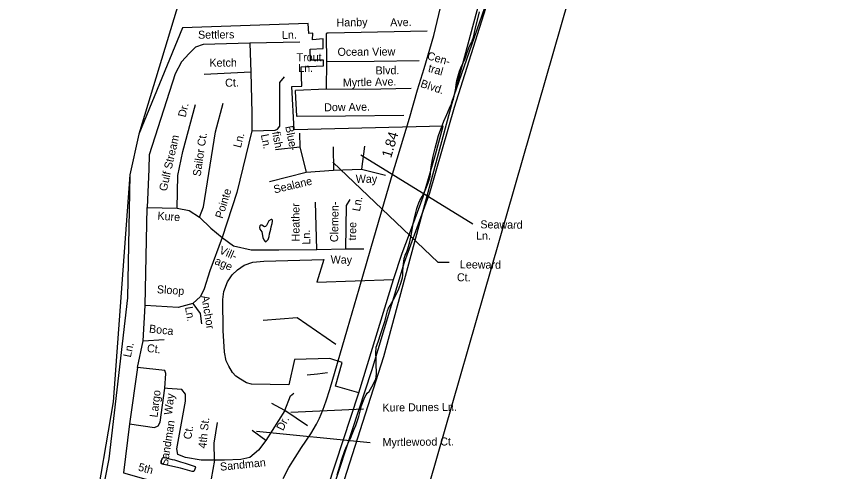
# Model space of a CAD drawing. Extents: x 1945482 to 2853149, y 66427 to 1015778.
# Drawn here: x 2329763 to 2336452, y 93966 to 97692 of the extents above; entities that cross this region are included whole.
import ezdxf

# ---------------------------------------------------------------- set-up
doc = ezdxf.new("R2010")
doc.units = 0
for name, color, linetype in [('Old_Level_10', 7, 'Continuous'), ('Old_Level_17', 7, 'Continuous'), ('Old_Level_28', 7, 'Continuous'), ('Old_Level_35', 7, 'Continuous'), ('Old_Level_48', 7, 'Continuous'), ('Old_Level_49', 7, 'Continuous'), ('Old_Level_52', 7, 'Continuous'), ('Old_Level_60', 7, 'Continuous'), ('Old_Level_61', 7, 'Continuous'), ('Old_Level_63', 7, 'Continuous')]:
    doc.layers.add(name, color=color, linetype=linetype)

msp = doc.modelspace()

# ---------------------------------------------------------------- linework, layer by layer
at = {"layer": 'Old_Level_10'}
for points in [[(2333502.8, 95992.6), (2332586.5, 96555.7)], [(2333310.2, 95677.3), (2333220.6, 95677.3), (2332356, 96500.1)], [(2332609.1, 94478.5), (2332011.8, 94449.5)], [(2332662.2, 94201.1), (2331731.4, 94294.3)]]:
    msp.add_lwpolyline(points, dxfattribs=at)
at = {"layer": 'Old_Level_28'}
msp.add_lwpolyline([(2331948.9, 93909.6), (2331995.8, 93998.4), (2332100.3, 94162.9), (2332175.5, 94275.1), (2332223.2, 94353.5), (2332247.8, 94402.6), (2332275.4, 94468.7), (2332303.1, 94545.6), (2332330.7, 94637.8), (2332395.5, 94853.6), (2332477, 95133.4), (2332572.2, 95460.7), (2332669, 95791.2), (2332838, 96372.2), (2332984, 96859.4), (2333050, 97090), (2333105.3, 97266.8), (2333183.7, 97535.7), (2333295.8, 98007.8)], dxfattribs=at)
at = {"layer": 'Old_Level_35'}
msp.add_line((2332304.7, 97319.1), (2332303, 97095.2), dxfattribs=at)
for points in [[(2333130.1, 97569.9), (2332722.5, 97561.7), (2332318.3, 97555.6), (2332306.3, 97553.5), (2332302.2, 97549.4)], [(2332302.2, 97549.4), (2332302.5, 97541.6), (2332304.7, 97319.1)], [(2332086.6, 97482.2), (2331675.2, 97473.8), (2331293.5, 97461), (2331229.9, 97439.8), (2331179, 97388.9), (2331115.4, 97321), (2331064.5, 97221.7), (2330852.5, 96559.6), (2330848.2, 96440.8), (2330835.5, 96126.7), (2331081.5, 96122.5), (2331085.7, 96389.8), (2331128.1, 96585.1), (2331229.9, 96971.3)], [(2331675.2, 97473.8), (2331683.7, 97234.4), (2331302, 97217.4)], [(2333062.6, 97327), (2332694.8, 97321.4), (2332304.7, 97319.1)], [(2331683.7, 97234.4), (2331692.2, 96899.1), (2331692.2, 96754.8), (2331569.2, 96249.8), (2331450.4, 95882.2), (2331348.7, 95610.6), (2331302, 95462.1), (2331272.3, 95398.4), (2331208.7, 95343.3), (2331089.9, 95309.3), (2330818.5, 95326.3), (2330835.5, 96126.7)], [(2331692.2, 96754.8), (2331883, 96760.8), (2331904.2, 96769.2), (2331921.2, 96794.7), (2331921.2, 97151.2), (2331959.4, 97197.9)], [(2332063.3, 96872.7), (2332061.2, 96876.6), (2332050.9, 97078.7), (2332051, 97084.6)], [(2332303, 97095.2), (2332053.2, 97086.7), (2332051, 97084.6)], [(2332999.2, 97102.3), (2332625, 97094.5), (2332303, 97095.2)], [(2331263.8, 96047.8), (2331297.8, 96132.6), (2331395.3, 96748), (2331458.9, 96981.4)], [(2332939.3, 96881.7), (2332459.4, 96874.9), (2332063.3, 96872.7)], [(2332082.3, 96735.3), (2332086.6, 96620.7), (2331887.3, 96599.5)], [(2332086.6, 96620.7), (2332137.5, 96417)], [(2332358, 96624.9), (2332362.3, 96434)], [(2332616.7, 96629.2), (2332591.3, 96442.5)], [(2331836.4, 96340.6), (2332137.5, 96417), (2332362.3, 96434), (2332591.3, 96442.5), (2332787.7, 96393.3)], [(2332226.5, 95784.6), (2332213.8, 96170.8)], [(2332464, 95788.9), (2332468.3, 96145.4), (2332498, 96192.1)], [(2331081.5, 96122.5), (2331179, 96102.9), (2331263.8, 96047.8), (2331357.1, 95958.6), (2331450.4, 95882.2), (2331543.7, 95814.3), (2331687.9, 95780.4), (2331912.7, 95780.4), (2332226.5, 95784.6), (2332464, 95788.9)], [(2332464, 95788.9), (2332609.9, 95788.9)], [(2331208.7, 95343.3), (2331268.1, 95260.9), (2331280.8, 95176)], [(2330801.6, 95036), (2330818.5, 95326.3)], [(2331785.5, 95205.7), (2332065.4, 95227)], [(2332065.4, 95227), (2332380.5, 95008)], [(2331806.7, 94221.1), (2331747.3, 94140.5), (2331675.2, 94081.1), (2331603.1, 94064.1), (2331467.4, 94059.9), (2331386.8, 94059.9), (2331276.6, 94059.9), (2331149.3, 94081.1), (2331085.7, 94106.5), (2331077.2, 94153.2), (2331149.3, 94543.7), (2331149.3, 94598.9), (2331119.6, 94637), (2331000.9, 94645.5), (2330979.7, 94649.8), (2330988.2, 94768.6), (2330979.7, 94794.1), (2330754.9, 94819.5), (2330801.6, 95036), (2330975.4, 95048.7)], [(2330754.9, 94819.5), (2330691.3, 94356.9), (2330894.9, 94327.2), (2330924.5, 94340), (2330941.5, 94369.7), (2330979.7, 94649.8)], [(2332313.1, 94774.8), (2332230.8, 94764.4), (2332146, 94755.9)], [(2331963.6, 94467.3), (2332010.3, 94586.1), (2332035.7, 94607.3)], [(2331963.6, 94467.3), (2331806.7, 94221.1), (2331696.4, 94301.8)], [(2332149.7, 94341), (2331963.6, 94467.3), (2331857.6, 94522.5)], [(2330691.3, 94356.9), (2330639.8, 93956.6), (2330805, 93910.6), (2330942.7, 93873.9), (2331016.1, 93800.4), (2331057.4, 93658.1), (2331042.2, 93559.4)], [(2331386.8, 94059.9), (2331383.2, 94198.1), (2331410.8, 94368)], [(2331386.8, 94059.9), (2331360.1, 93906.5)]]:
    msp.add_lwpolyline(points, dxfattribs=at)
at = {"layer": 'Old_Level_48'}
for points in [[(2333261.7, 96792.4), (2332039.5, 96763.6), (2332021.5, 97117), (2332101.4, 97120.1), (2332097.1, 97280), (2332280.9, 97287.3), (2332279.1, 97333.2), (2332173, 97335), (2332171.5, 97423), (2332277.3, 97429.2), (2332276.1, 97509.2), (2332190.5, 97499.8), (2332192.3, 97553.9), (2332160.5, 97550.6), (2332155.1, 97634.4), (2331125.7, 97599.6)], [(2331125.7, 97599.6), (2330766.3, 96729.3), (2330693.4, 96396.3), (2330556.8, 94536.2), (2330233, 92650)], [(2332570.7, 94609.9), (2332378.3, 94666.1), (2332432.8, 94858.4), (2332331.4, 94892.4), (2332043.6, 94883), (2331995.8, 94677), (2331689.4, 94683), (2331649, 94693.4), (2331599.9, 94721.4), (2331560.8, 94747.9), (2331535.6, 94776.9), (2331503.6, 94829.7), (2331481.8, 94872.8), (2331469, 94944.4), (2331458.1, 95120), (2331454.1, 95373.9), (2331463.4, 95440.3), (2331492.3, 95519.5), (2331532.1, 95577.1), (2331574.5, 95618.8), (2331629, 95654.9), (2331700.1, 95679.8), (2331791.8, 95687.4), (2332283.4, 95702.8), (2332224.7, 95516.4), (2332852.8, 95539.3), (2332925.8, 95755), (2332984.3, 95912.6), (2333097.5, 96215.1), (2333196.5, 96561.4), (2333261.7, 96792.4)], [(2331997.2, 92866.6), (2332570.7, 94609.9)]]:
    msp.add_lwpolyline(points, dxfattribs=at)
at = {"layer": 'Old_Level_49'}
for points in [[(2331284.7, 98437.7), (2330766.3, 96729.3), (2330693.4, 96396.3), (2330674.6, 95387.2), (2330521.2, 94071.3)], [(2333330.1, 96982.7), (2333602, 97763.5), (2331284.7, 98437.7)], [(2332570.7, 94609.9), (2332852.8, 95539.3), (2332925.8, 95755), (2332984.3, 95912.6), (2333097.5, 96215.1), (2333196.5, 96561.4)], [(2331997.2, 92866.6), (2332570.7, 94609.9)], [(2330521.2, 94071.3), (2330338.5, 93140.4)]]:
    msp.add_lwpolyline(points, dxfattribs=at)
at = {"layer": 'Old_Level_52'}
msp.add_lwpolyline([(2328696.2, 82510.1), (2328851.1, 82629.4), (2329056.8, 82754.6), (2329140.2, 82948.5), (2329298.2, 83324.2), (2329521.7, 83807.2), (2329599.2, 84075.6), (2329780.9, 84734.6), (2330069.9, 85774.1), (2330486.3, 87434.7), (2331265, 90397.2), (2331649.5, 91610.8), (2331855.1, 92031.3), (2332774.3, 94909.4), (2333577.6, 97883.8)], dxfattribs=at)
at = {"layer": 'Old_Level_60'}
for points in [[(2332922, 95534.6), (2332926.2, 95552.5), (2332929.2, 95573.1), (2332931, 95595.6), (2332932.7, 95644.1), (2332941.7, 95710.1), (2332949.2, 95737.8), (2332956.5, 95752.3), (2332970, 95788.2), (2332977.5, 95808.8), (2332988.7, 95845.9), (2332999.5, 95897.9), (2333014, 95993.5), (2333030, 96065.5), (2333044.7, 96119), (2333052, 96143.4), (2333060.2, 96164.7), (2333070.5, 96185.5), (2333089.2, 96217.4), (2333097, 96233.8), (2333118, 96281.1), (2333137.2, 96328.4), (2333146.5, 96353.3), (2333153.2, 96381.5), (2333162, 96459.8), (2333172, 96521.1), (2333177.7, 96548.1), (2333194.5, 96612.8), (2333207.2, 96655.2), (2333222.5, 96717.5), (2333264.7, 96834.9), (2333291.7, 96888.2), (2333313.7, 96941.7), (2333335, 96987.3), (2333344.2, 97014.4), (2333358.7, 97077.4), (2333363.5, 97103.7), (2333367.5, 97135.8), (2333372.5, 97166.6), (2333394, 97244.7), (2333404, 97272.1), (2333425, 97312.7), (2333437, 97338.3), (2333447.2, 97364), (2333472.2, 97433.3), (2333483.2, 97458.1), (2333494.7, 97481.2), (2333502, 97500.2), (2333508.7, 97522.3), (2333521.5, 97584.7), (2333559.2, 97728.9)], [(2331806.5, 95847.7), (2331813, 95851), (2331826.5, 95867), (2331834, 95890.5), (2331836.7, 95911.5), (2331847.5, 95949.6), (2331851.5, 95969.4), (2331858.5, 95995.6), (2331863, 96016.1), (2331861.7, 96023.6), (2331857.2, 96028.3), (2331850.7, 96028.5), (2331832.5, 96017.4), (2331822.5, 96002.1), (2331814, 95981.5), (2331805.5, 95973.2), (2331795.7, 95970.6), (2331774.5, 95982.8), (2331766.5, 95984.4), (2331759.2, 95977.3), (2331756.2, 95963.9), (2331757.5, 95950.6), (2331773.5, 95928.8), (2331782.7, 95881.6), (2331791, 95862.3), (2331801, 95848.9), (2331806.5, 95847.7)], [(2332391.2, 93940.1), (2332404, 93976.2), (2332415, 94010.6), (2332427.5, 94059), (2332454.5, 94138.4), (2332470.2, 94176), (2332481, 94197.6), (2332501.7, 94236), (2332516.2, 94271.9), (2332531, 94314.6), (2332544.5, 94344.5), (2332565, 94402), (2332569.5, 94416.5), (2332591.7, 94505.7), (2332601, 94535.6), (2332617.5, 94574.9), (2332628.7, 94594.2), (2332638, 94607.2), (2332653.2, 94620.9), (2332675.5, 94658.6), (2332705.5, 94717.4), (2332712, 94738.4), (2332714.2, 94769.7), (2332713.5, 94798.2), (2332712, 94818), (2332711.7, 94876.3), (2332709.5, 94948), (2332710.5, 94967.6), (2332712.7, 94983.6), (2332716.7, 94999.4), (2332732.5, 95043.7), (2332743.5, 95079), (2332786.5, 95201.7), (2332793.7, 95238.5), (2332805.5, 95283.2), (2332813.7, 95303.9), (2332827.5, 95325.9), (2332865.2, 95392.6), (2332896.5, 95462.4), (2332916.5, 95517.2), (2332922, 95534.6)], [(2331216.5, 93968.1), (2331203.5, 93968.1), (2331107.2, 93994.5), (2330972.7, 94025.1), (2330955, 94031.1), (2330952.2, 94036.4), (2330953.7, 94052.2), (2330959.2, 94074), (2330962.5, 94079), (2330967.2, 94081.3), (2330989, 94077.7), (2331040.5, 94065.5), (2331058.5, 94061.1), (2331090.5, 94051.6), (2331109, 94045.2), (2331145.7, 94035.4), (2331220.7, 94011.2), (2331227.2, 94007.5), (2331230.5, 94001.9), (2331226.7, 93985.6), (2331219.5, 93972.2), (2331216.5, 93968.1)]]:
    msp.add_lwpolyline(points, dxfattribs=at)
at = {"layer": 'Old_Level_61'}
msp.add_lwpolyline([(2329234.8, 82617.4), (2329331.5, 82719.1), (2329646.5, 83628), (2329829.8, 84449.9), (2330005.8, 85191.7), (2330114.4, 85937), (2330271.3, 86752.9), (2330497.1, 87342.8), (2330607.2, 88124.5), (2330847.3, 88981.5), (2330879.1, 89217.6), (2331215.8, 90241.5), (2331368.7, 90776), (2331514.3, 91171), (2331523.1, 91257.6), (2331584, 91404.9), (2331811.9, 91738.7), (2332038.6, 92852.7), (2332676.8, 94792.5), (2332942.7, 95679.1), (2333152.3, 96247.5), (2333354.1, 96950.2), (2335005.7, 102164.1)], dxfattribs=at)
at = {"layer": 'Old_Level_63'}
msp.add_lwpolyline([(2336452.5, 105360.7), (2330407.8, 84355.1), (2324283.6, 66611.7), (2319636.9, 66611.7), (2318954.8, 83559.4), (2323249.7, 105360.7)], dxfattribs=at)

# ---------------------------------------------------------------- texts
at = {"layer": 'Old_Level_10'}
for s, height, rotation, p in [('Hanby', 65.62, 1.1522, (2332387.3, 97608.4)), ('Ave.', 65.62, 1.1522, (2332826.8, 97609.6)), ('Settlers', 65.62, 0.62777, (2331252.3, 97508.8)), ('Ln.', 65.62, 1.41619, (2331939.7, 97507.1)), ('Ocean View', 65.62, 0.33147, (2332395.4, 97368.9)), ('Ketch', 65.62, 0.26786, (2331345.4, 97279.9)), ('Cen-', 65.62, 343.92611, (2333123.9, 97342.1)), ('Blvd.', 65.62, 0.87819, (2332707.2, 97216.3)), ('tral', 65.62, 343.92611, (2333132.6, 97240.5)), ('Ct.', 65.62, 1.60964, (2331474.6, 97115.3)), ('Myrtle Ave.', 65.617, 1.20399, (2332439, 97117.6)), ('Blvd.', 65.62, 341.54968, (2333069.3, 97115.6)), ('Dr.', 65.62, 77.25998, (2331149.9, 96862.3)), ('Dow Ave.', 65.62, 0.80957, (2332285.9, 96915)), ('fish ', 65.62, 281.05194, (2331858.3, 96743.7)), ('Blue-', 65.62, 281.05194, (2331966.1, 96790.5)), ('Gulf Stream', 65.617, 77.25998, (2330994.7, 96257.1)), ('Sailor Ct.', 65.62, 81.60252, (2331272.4, 96379)), ('Ln.', 65.62, 75.63914, (2331602.4, 96611.4)), ('Ln.', 65.62, 281.05194, (2331766.1, 96722.8)), ('Sealane', 65.62, 13.26373, (2331878.8, 96242.5)), ('Pointe', 65.62, 72.92882, (2331452.8, 96032.8)), ('Ln.', 65.62, 80.01952, (2332578.5, 96092.5)), ('Heather', 65.62, 90.05531, (2332083.4, 95850.4)), ('Clemen-', 65.62, 89.09508, (2332399.3, 95843.9)), ('Kure', 65.62, 355.64976, (2330917.5, 96029.3)), ('tree', 65.62, 89.09508, (2332546.5, 95857.8)), ('Seaward ', 65.62, 359.45168, (2333565.1, 95957.2)), ('Ln.', 65.62, 91.7139, (2332172.5, 95825)), ('Ln.', 65.62, 359.54394, (2333529.5, 95864.8)), ('Vill-', 65.62, 336.46216, (2331419.8, 95754.2)), ('Way', 65.62, 359.26324, (2332338, 95669.7)), ('age', 65.62, 336.46216, (2331382.3, 95666.8)), ('Leeward', 65.62, 359.45168, (2333397.6, 95629.7)), ('Ct.', 65.62, 359.54394, (2333373.2, 95523.9)), ('Sloop', 65.62, 356.1818, (2330913, 95426.5)), ('Anchor', 65.62, 279.63622, (2331277.3, 95403)), ('Ln.', 65.62, 279.63622, (2331144.8, 95311.9)), ('Boca ', 65.62, 353.72016, (2330847.8, 95104.9)), ('Ln.', 65.62, 77.8985, (2330700.4, 94896.9)), ('Ct.', 65.62, 353.72016, (2330830.7, 94945.7)), ('Largo ', 65.62, 83.20696, (2330919.7, 94407.1)), ('Way', 65.62, 83.20696, (2331037.7, 94427.4)), ('Kure Dunes Ln.', 65.617, 0.61352, (2332763.1, 94457.1)), ('4th St.', 65.62, 83.97438, (2331317.9, 94153.4)), ('Dr.', 65.62, 62.31828, (2331947.3, 94295.5)), ('Sandman', 65.62, 81.10631, (2331003.5, 94009.7)), ('Ct.', 65.62, 81.10631, (2331195.4, 94226.5)), ('Myrtlewood Ct.', 65.617, 0.61352, (2332764, 94174.1)), ('Sandman', 65.62, 5.74151, (2331435.4, 93973)), ('5th', 65.62, 345.02267, (2330756.7, 93975.6))]:
    msp.add_text(s, height=height, rotation=rotation, dxfattribs=at).set_placement(p)
for s, p in [('Trout', (2332059.3, 97325)), ('Ln.', (2332073, 97237.4)), ('Way', (2332544.2, 96329.5))]:
    msp.add_text(s, height=65.62, dxfattribs=at).set_placement(p)
at = {"layer": 'Old_Level_17'}
msp.add_text('1.84', height=82.02, rotation=73.32428, dxfattribs=at).set_placement((2332833.4, 96528.3))

doc.saveas('drawing.dxf')
